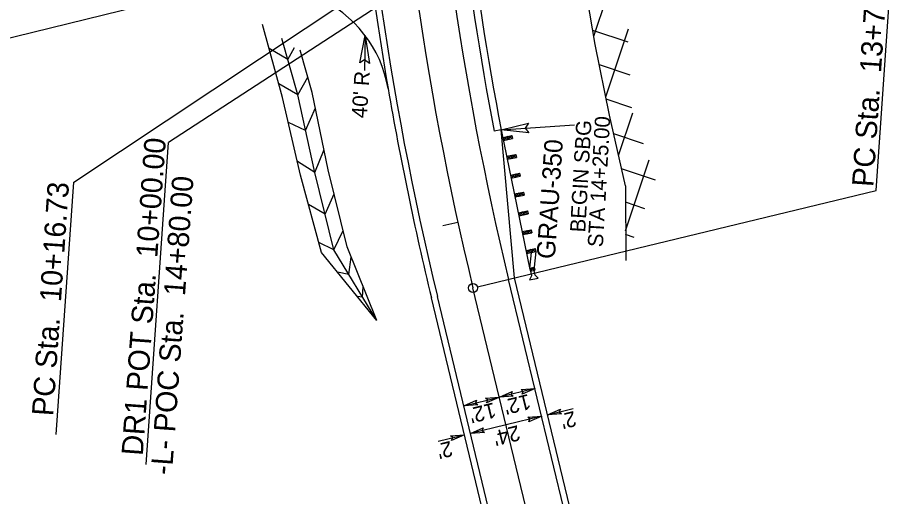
# Model space of a CAD drawing. Extents: x 2599146 to 2600072, y 728518 to 730269.
# Drawn here: x 2599320.7 to 2599607.2, y 728920 to 729076.9 of the extents above; entities that cross this region are included whole.
import ezdxf

# ---------------------------------------------------------------- set-up
doc = ezdxf.new("R2010")
doc.units = 0
for name, color, linetype in [('Default', 7, 'Continuous'), ('Prop Conc Shoulder Berm Gutter', 7, 'Continuous'), ('Prop Dimension', 7, 'Continuous'), ('Prop Dimension Text', 7, 'Continuous'), ('Prop Drainage Ditch Base Lines', 7, 'Continuous'), ('Prop EOT', 7, 'Continuous'), ('Prop Guardrail', 7, 'Continuous'), ('Prop Guardrail Anchor Unit CELL', 7, 'Continuous'), ('Prop Horizontal Alignment', 7, 'Continuous'), ('Prop Horizontal Alignment Station Label', 7, 'Continuous'), ('Prop Horizontal Alignment Tick Small', 7, 'Continuous'), ('Prop Structure Anchor Unit CELL', 7, 'Continuous'), ('Prop Terminator CELL', 7, 'Continuous')]:
    doc.layers.add(name, color=color, linetype=linetype)

msp = doc.modelspace()

# ---------------------------------------------------------------- linework, layer by layer
at = {"layer": 'Default'}
for p, q in [((2599509.38, 729070.78), (2599522.44, 729110.03)), ((2599509.85, 729068.07), (2599505.83, 729091.4)), ((2599520.59, 729068.8), (2599509.06, 729072.63)), ((2599513.3, 729050.88), (2599520.71, 729073.14)), ((2599514.51, 729044.86), (2599509.85, 729068.07)), ((2599521.26, 729058.03), (2599511.19, 729061.38)), ((2599521.84, 729047.3), (2599513.46, 729050.09)), ((2599517.47, 729031.72), (2599522.11, 729045.68)), ((2599519.71, 729021.78), (2599514.51, 729044.86)), ((2599525.67, 729035.49), (2599515.88, 729038.74)), ((2599519.79, 729007.02), (2599527.51, 729030.23)), ((2599529.58, 729023.65), (2599518.45, 729027.35)), ((2599519.71, 729021.78), (2599519.85, 728997.32)), ((2599526.11, 729014.27), (2599519.74, 729016.39)), ((2599522.64, 729004.88), (2599519.8, 729005.83))]:
    msp.add_line(p, q, dxfattribs=at)
at = {"layer": 'Prop Conc Shoulder Berm Gutter'}
msp.add_line((2599479.05, 729040.1), (2599476.75, 729039.67), dxfattribs=at)
msp.add_arc((2600480.74, 729232.47), 1022.34, 182.39886, 190.87052, dxfattribs=at)
at = {"layer": 'Prop Dimension'}
for p, q in [((2599479.05, 729040.1), (2599503.09, 729041.69)), ((2599490.12, 728955.32), (2599478.46, 728952.51)), ((2599466.79, 728949.69), (2599478.46, 728952.51)), ((2599494.24, 728946.78), (2599502.56, 728948.79)), ((2599492.3, 728946.31), (2599468.97, 728940.68)), ((2599458.4, 728938.13), (2599467.03, 728940.21))]:
    msp.add_line(p, q, dxfattribs=at)
at = {"layer": 'Prop Dimension Text'}
msp.add_line((2599434.5, 729070.97), (2599434.24, 729059.58), dxfattribs=at)
at = {"layer": 'Prop Drainage Ditch Base Lines'}
for p, q in [((2599407.45, 729050.73), (2599400.91, 729074.55)), ((2599412.44, 729051.57), (2599407.26, 729070)), ((2599409.17, 729063.19), (2599403.07, 729066.71)), ((2599409.17, 729063.19), (2599411.38, 729067.04)), ((2599417.16, 729052.37), (2599413.17, 729066.2)), ((2599412.44, 729051.57), (2599415.73, 729057.32)), ((2599412.44, 729051.57), (2599406.24, 729055.15)), ((2599418.02, 729026.13), (2599412.44, 729051.57)), ((2599422.44, 729026.98), (2599417.16, 729052.37)), ((2599413.36, 729025.22), (2599407.45, 729050.73)), ((2599415.01, 729039.84), (2599418.22, 729047.27)), ((2599415.01, 729039.84), (2599409.35, 729042.53)), ((2599418.02, 729026.13), (2599421.04, 729033.68)), ((2599418.02, 729026.13), (2599412.32, 729029.72)), ((2599424.19, 729000.84), (2599418.02, 729026.13)), ((2599428.57, 729001.8), (2599422.44, 729026.98)), ((2599420.16, 728999.96), (2599413.36, 729025.22)), ((2599421.36, 729012.44), (2599424.34, 729019.17)), ((2599421.36, 729012.44), (2599415.93, 729015.66)), ((2599424.19, 729000.84), (2599427.29, 729007.08)), ((2599424.19, 729000.84), (2599419.28, 729003.24)), ((2599438.35, 728977.64), (2599420.16, 728999.96)), ((2599438.35, 728977.64), (2599424.19, 729000.84)), ((2599438.35, 728977.64), (2599428.57, 729001.8)), ((2599429.16, 728992.69), (2599429.96, 728998.37)), ((2599429.16, 728992.69), (2599425.46, 728993.45)), ((2599433.66, 728985.32), (2599433.89, 728988.66)), ((2599433.66, 728985.32), (2599431.91, 728985.53))]:
    msp.add_line(p, q, dxfattribs=at)
at = {"layer": 'Prop EOT'}
for p, q in [((2599483.42, 728991.6), (2599479.05, 729040.1)), ((2599517.39, 728842.41), (2599481.48, 728991.13)), ((2599519.34, 728842.88), (2599483.42, 728991.6)), ((2599494.06, 728836.78), (2599458.15, 728985.49)), ((2599492.12, 728836.31), (2599456.2, 728985.02))]:
    msp.add_line(p, q, dxfattribs=at)
for centre, radius, start, end in [((2600480.74, 729232.47), 1028, 182.39886, 193.57808), ((2600480.74, 729232.47), 1052, 182.39886, 193.57808), ((2600480.74, 729232.47), 1054, 186.68017, 189.77021), ((2599402.61, 729046.82), 40, 9.7702, 66.3139), ((2600480.74, 729232.47), 1054, 189.77021, 193.57808)]:
    msp.add_arc(centre, radius, start, end, dxfattribs=at)
at = {"layer": 'Prop Guardrail'}
msp.add_arc((2600478.29, 729232.3), 1017.56, 182.67771, 190.88783, dxfattribs=at)
at = {"layer": 'Prop Guardrail Anchor Unit CELL'}
for p, q in [((2599479.05, 729040.1), (2599488.46, 728994.31)), ((2599479.56, 729037.61), (2599482.5, 729038.21)), ((2599479.56, 729037.61), (2599479.76, 729036.63)), ((2599481.23, 729036.93), (2599479.56, 729037.61)), ((2599481.03, 729037.91), (2599479.76, 729036.63)), ((2599479.76, 729036.63), (2599482.7, 729037.23)), ((2599479.76, 729036.63), (2599481.23, 729036.93)), ((2599481.03, 729037.91), (2599481.23, 729036.93)), ((2599482.7, 729037.23), (2599481.03, 729037.91)), ((2599481.23, 729036.93), (2599482.5, 729038.21)), ((2599482.5, 729038.21), (2599482.7, 729037.23)), ((2599480.83, 729031.44), (2599483.82, 729032.05)), ((2599480.83, 729031.44), (2599482.53, 729030.76)), ((2599482.33, 729031.74), (2599481.03, 729030.46)), ((2599482.33, 729031.74), (2599482.53, 729030.76)), ((2599484.02, 729031.07), (2599482.33, 729031.74)), ((2599482.53, 729030.76), (2599483.82, 729032.05)), ((2599483.82, 729032.05), (2599484.02, 729031.07)), ((2599481.03, 729030.46), (2599484.02, 729031.07)), ((2599482.1, 729025.26), (2599485.08, 729025.88)), ((2599483.59, 729025.57), (2599482.3, 729024.29)), ((2599483.59, 729025.57), (2599483.79, 729024.59)), ((2599485.29, 729024.9), (2599483.59, 729025.57)), ((2599483.79, 729024.59), (2599485.08, 729025.88)), ((2599485.08, 729025.88), (2599485.29, 729024.9)), ((2599482.1, 729025.26), (2599483.79, 729024.59)), ((2599482.3, 729024.29), (2599485.29, 729024.9)), ((2599483.37, 729019.09), (2599486.34, 729019.7)), ((2599485.06, 729018.42), (2599486.34, 729019.7)), ((2599486.34, 729019.7), (2599486.54, 729018.72)), ((2599483.37, 729019.09), (2599483.57, 729018.11)), ((2599483.37, 729019.09), (2599485.06, 729018.42)), ((2599484.85, 729019.4), (2599483.57, 729018.11)), ((2599483.57, 729018.11), (2599486.54, 729018.72)), ((2599484.85, 729019.4), (2599485.06, 729018.42)), ((2599486.54, 729018.72), (2599484.85, 729019.4)), ((2599484.64, 729012.92), (2599487.71, 729013.55)), ((2599484.64, 729012.92), (2599486.37, 729012.26)), ((2599486.17, 729013.24), (2599484.84, 729011.94)), ((2599484.84, 729011.94), (2599487.91, 729012.57)), ((2599486.17, 729013.24), (2599486.37, 729012.26)), ((2599487.91, 729012.57), (2599486.17, 729013.24)), ((2599486.37, 729012.26), (2599487.71, 729013.55)), ((2599487.71, 729013.55), (2599487.91, 729012.57)), ((2599485.9, 729006.75), (2599488.84, 729007.35)), ((2599485.9, 729006.75), (2599487.58, 729006.07)), ((2599487.37, 729007.05), (2599486.11, 729005.77)), ((2599486.11, 729005.77), (2599489.04, 729006.37)), ((2599487.37, 729007.05), (2599487.58, 729006.07)), ((2599489.04, 729006.37), (2599487.37, 729007.05)), ((2599487.58, 729006.07), (2599488.84, 729007.35)), ((2599488.84, 729007.35), (2599489.04, 729006.37)), ((2599487.17, 729000.58), (2599490.17, 729001.19)), ((2599487.17, 729000.58), (2599488.88, 728999.9)), ((2599488.67, 729000.88), (2599487.37, 728999.6)), ((2599487.37, 728999.6), (2599490.38, 729000.21)), ((2599488.88, 728999.9), (2599488.36, 728994.8)), ((2599488.67, 729000.88), (2599488.88, 728999.9)), ((2599490.38, 729000.21), (2599488.67, 729000.88)), ((2599488.88, 728999.9), (2599490.17, 729001.19)), ((2599490.38, 729000.21), (2599489.83, 728995.1)), ((2599490.17, 729001.19), (2599490.38, 729000.21)), ((2599488.36, 728994.8), (2599489.83, 728995.1)), ((2599490.03, 728994.12), (2599488.36, 728994.8)), ((2599489.14, 728994.4), (2599488.54, 728994.29)), ((2599488.54, 728994.29), (2599488.92, 728992.28)), ((2599488.56, 728993.82), (2599489.83, 728995.1)), ((2599488.56, 728993.82), (2599490.03, 728994.12)), ((2599489.74, 728994.51), (2599489.14, 728994.4)), ((2599490.12, 728992.5), (2599489.74, 728994.51)), ((2599489.83, 728995.1), (2599489.93, 728994.61)), ((2599489.83, 728995.1), (2599490.03, 728994.12)), ((2599488.92, 728992.28), (2599488.29, 728990.96)), ((2599488.29, 728990.96), (2599491.18, 728991.5)), ((2599491.18, 728991.5), (2599490.12, 728992.5))]:
    msp.add_line(p, q, dxfattribs=at)
at = {"layer": 'Prop Horizontal Alignment'}
msp.add_line((2599558.55, 728620.88), (2599469.81, 728988.31), dxfattribs=at)
msp.add_arc((2600480.74, 729232.47), 1040, 170.73628, 193.57808, dxfattribs=at)
at = {"layer": 'Prop Horizontal Alignment Station Label'}
for p, q in [((2599601.83, 729020.2), (2599607.18, 729097.66)), ((2599290.96, 729063.51), (2599412.76, 729093.55)), ((2599450.76, 729088.48), (2599370.11, 729036)), ((2599339.07, 729022.96), (2599434.19, 729086.17)), ((2599362.82, 728930.47), (2599370.11, 729036)), ((2599333.36, 728940.29), (2599339.07, 729022.96)), ((2599471.27, 728988.66), (2599601.83, 729020.2))]:
    msp.add_line(p, q, dxfattribs=at)
msp.add_circle((2599469.81, 728988.31), 1.5, dxfattribs=at)
at = {"layer": 'Prop Horizontal Alignment Tick Small'}
msp.add_line((2599464.87, 729009.76), (2599459.99, 729008.69), dxfattribs=at)
at = {"layer": 'Prop Terminator CELL'}
for points in [[(2599432.74, 729062.01), (2599434.5, 729070.97), (2599435.89, 729061.88), (2599434.32, 729063.07)], [(2599488.13, 729039.15), (2599479.05, 729040.1), (2599487.97, 729042.29), (2599486.93, 729040.62)], [(2599483.02, 728952.81), (2599478.46, 728952.51), (2599482.67, 728954.35), (2599482.3, 728953.43)], [(2599485.57, 728955.02), (2599490.12, 728955.32), (2599485.91, 728953.48), (2599486.28, 728954.4)], [(2599471.35, 728949.99), (2599466.79, 728949.69), (2599471.01, 728951.53), (2599470.63, 728950.62)], [(2599473.9, 728952.2), (2599478.46, 728952.51), (2599474.25, 728950.67), (2599474.62, 728951.58)], [(2599498.8, 728947.09), (2599494.24, 728946.78), (2599498.45, 728948.62), (2599498.08, 728947.71)], [(2599487.74, 728946.01), (2599492.3, 728946.31), (2599488.09, 728944.47), (2599488.46, 728945.39)], [(2599473.53, 728940.98), (2599468.97, 728940.68), (2599473.18, 728942.52), (2599472.81, 728941.61)], [(2599462.47, 728939.91), (2599467.03, 728940.21), (2599462.82, 728938.37), (2599463.19, 728939.28)]]:
    msp.add_lwpolyline(points, close=True, dxfattribs=at)

# ---------------------------------------------------------------- texts
at = {"layer": 'Prop Dimension Text'}
for s, rotation, p in [("40' R", 86.05, (2599435, 729043.8)), ('BEGIN SBG', 86.7377, (2599506.56, 729006.43)), ('STA 14+25.00', 86.7377, (2599512.33, 729001.56)), ("12'", 193.9129, (2599487.99, 728953.64)), ("12'", 193.9129, (2599476.61, 728950.86)), ("2'", 193.9129, (2599502.92, 728948.07)), ("24'", 193.9129, (2599484.5, 728943.4)), ("2'", 193.9129, (2599462.42, 728938.26))]:
    msp.add_text(s, height=5, rotation=rotation, dxfattribs=at).set_placement(p)
at = {"layer": 'Prop Horizontal Alignment Station Label'}
for s, rotation, p in [('PC Sta.  13+77.99', 86.1217, (2599600.88, 729021.28)), ('DR1 POT Sta.  10+00.00', 85.8246, (2599361.68, 728933.22)), ('PC Sta.  10+16.73', 86.1013, (2599332.34, 728946.21)), ('-L- POC Sta.  14+80.00', 85.8246, (2599371.21, 728926.91))]:
    msp.add_text(s, height=7, rotation=rotation, dxfattribs=at).set_placement(p)
at = {"layer": 'Prop Structure Anchor Unit CELL'}
msp.add_text('GRAU-350', height=6, rotation=86.0601, dxfattribs=at).set_placement((2599496.59, 728997.64))

doc.saveas('drawing.dxf')
